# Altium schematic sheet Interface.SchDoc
size 203 x 165 mm; SheetNumber: 1; SheetTotal: 1
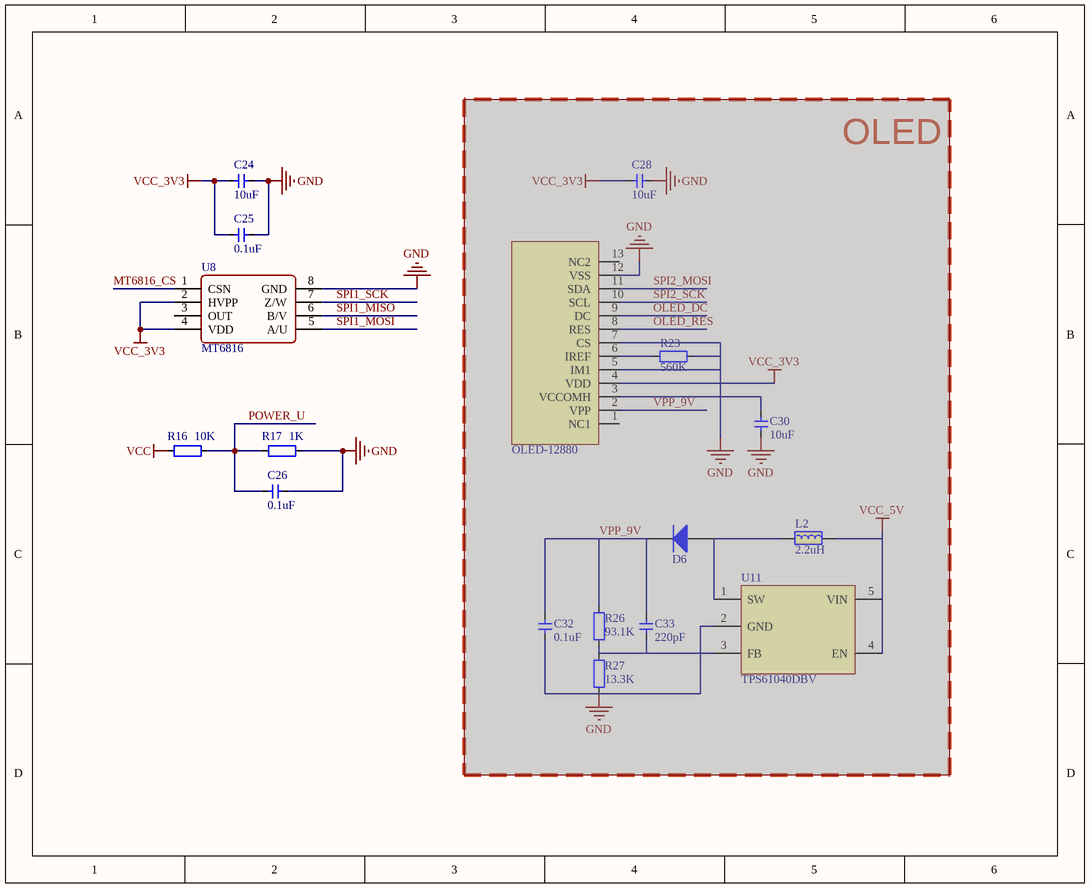
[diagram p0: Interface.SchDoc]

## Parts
1  OLED-12880  [OLED-12880]  (masked out: inside a compile mask, not in the netlist)
C24  10uF  [CAP_0402]
C25  0.1uF  [CAP_0402]
C26  0.1uF  [CAP_0402]
C28  10uF  [CAP_0402]  (masked out: inside a compile mask, not in the netlist)
C30  10uF  [CAP_0402]  (masked out: inside a compile mask, not in the netlist)
C32  0.1uF  [CAP_0402]  (masked out: inside a compile mask, not in the netlist)
C33  220pF  [CAP_0402]  (masked out: inside a compile mask, not in the netlist)
D6  二极管-5B5819WS  [SOD-323]  (value not drawn)  (masked out: inside a compile mask, not in the netlist)
L2  2.2uH  [2520-L]  (masked out: inside a compile mask, not in the netlist)
R16  10K  [RES_0402]
R17  1K  [RES_0402]
R23  560K  [RES_0402]  (masked out: inside a compile mask, not in the netlist)
R26  93.1K  [RES_0402]  (masked out: inside a compile mask, not in the netlist)
R27  13.3K  [RES_0402]  (masked out: inside a compile mask, not in the netlist)
U8  MT6816  [SO-8]
U11  TPS61040DBV  [SOT23-5]  (masked out: inside a compile mask, not in the netlist)

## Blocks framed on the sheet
OLED: 1 C28 C30 C32 C33 D6 L2 R23 R26 R27 U11

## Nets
GND: C24.1 C25.1 C26.1 R17.2 U8.8(GND)
VCC: R16.1
VCC_3V3: C24.2 C25.2 U8.2(HVPP) U8.4(VDD)
MT6816_CS: U8.1(CSN)
POWER_U: C26.2 R16.2 R17.1
SPI1_MISO: U8.6(B/V)
SPI1_MOSI: U8.5(A/U)
SPI1_SCK: U8.7(Z/W)

Not connected (* = marked no-connect by the designer): U8 3(OUT)

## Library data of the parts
C24-C26 C28 C30 C32 C33 = 电容-0402: Capacitor; Value: 0.1u
D6 = 二极管-5B5817WS: 40V
L2 = 电感-2520: 磁珠
R16 R17 R23 R26 R27 = 电阻-0402: Resistor; Value: 22R
U8 = MT6816: Magnetic Position Sensor
U11 = TPS61040DBV: MP: TPS61221DCK; MF: Texas Instruments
